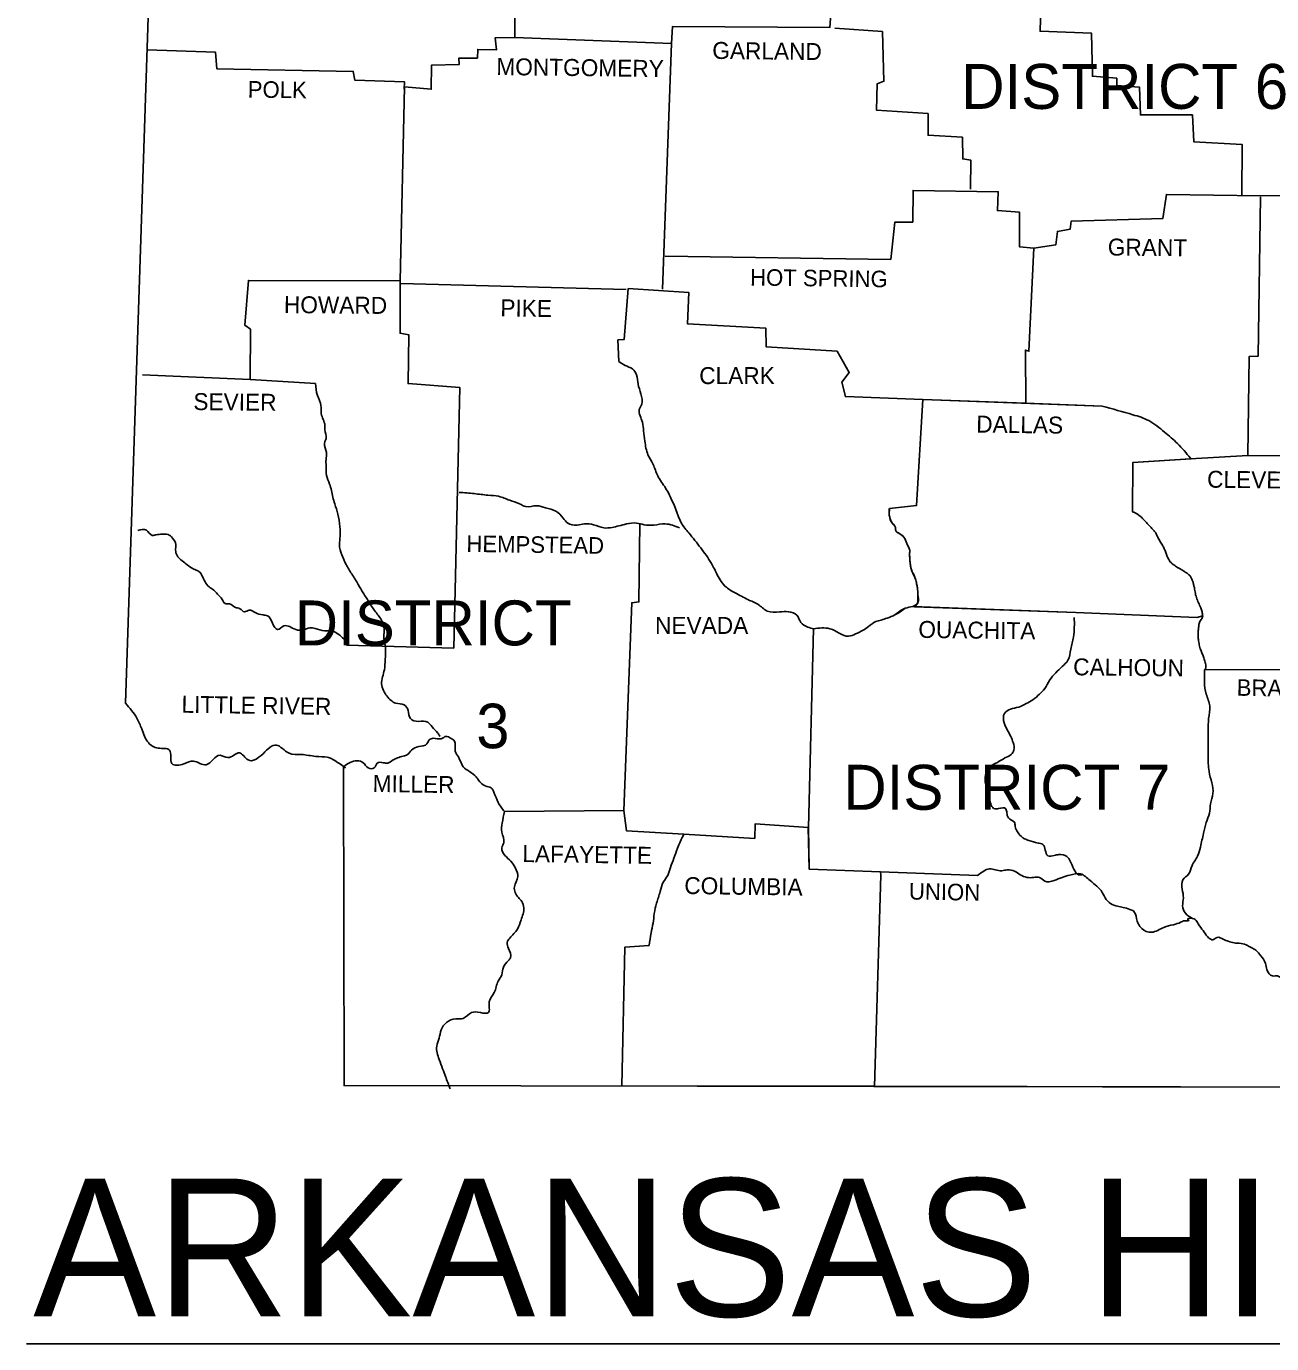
# Model space of a CAD drawing. Extents: x -17742 to 32032, y -17264 to 5867.
# Drawn here: x -17742 to -16002, y -10461 to -8621 of the extents above; entities that cross this region are included whole.
import ezdxf

# ---------------------------------------------------------------- set-up
doc = ezdxf.new("R2010")
doc.units = 0
for name, color, linetype in [('1', 7, 'Continuous'), ('2', 7, 'Continuous'), ('3', 7, 'Continuous'), ('R_Annotation', 7, 'Continuous')]:
    doc.layers.add(name, color=color, linetype=linetype)

msp = doc.modelspace()

# ---------------------------------------------------------------- linework, layer by layer
at = {"layer": '1'}
msp.add_line((-17741.9, -10460.7), (-14228.8, -10460.7), dxfattribs=at)
for points in [[(-17667.8, -7158.5), (-17553.9, -8073.2), (-17603.4, -9566.3)], [(-17058.6, -8314.8), (-17059.7, -8636.8), (-17087.2, -8637.3), (-17085, -8653.9), (-17111.4, -8653.3), (-17111.9, -8665.4), (-17137.8, -8665.4), (-17137.3, -8674.2), (-17175.8, -8675.3), (-17176.3, -8708.9), (-17213.8, -8705.6), (-17219.8, -8976.4), (-17431.7, -8975.8), (-17436.7, -9038.6), (-17428.9, -9044.1), (-17429.5, -9114.5), (-17579.7, -9107.9)], [(-16434.5, -8557), (-16614.4, -8551.5), (-16619.4, -8622.5), (-16839.5, -8621.4), (-16840.6, -8645.1)], [(-16385.5, -8555.3), (-16323.8, -8559.2), (-16326, -8628), (-16253.9, -8630.7), (-16252.8, -8690.7), (-16218.7, -8693.5), (-16218.7, -8703.9), (-16186.8, -8706.1), (-16185.7, -8744.7), (-16113.1, -8744.7), (-16110.9, -8782.6), (-16043.7, -8785.9), (-16044.3, -8857.5)], [(-16612.8, -8623.6), (-16546.2, -8628.5), (-16544, -8697.9), (-16553.3, -8701.2), (-16554.4, -8738.1), (-16482.3, -8743), (-16482.3, -8773.3), (-16434.5, -8776), (-16433.9, -8806.3), (-16422.4, -8808), (-16422.9, -8848.7)], [(-16840.6, -8645.1), (-17059.7, -8636.8)], [(-16840.6, -8645.1), (-16853.3, -8987.9)], [(-17573.1, -8653.9), (-17477.9, -8657.2), (-17475.7, -8680.3), (-17285.3, -8684.1), (-17283.1, -8696.2), (-17213.8, -8698.4), (-17214.3, -8708.9)], [(-15387.7, -8794.2), (-15595.7, -8788.7), (-15596.8, -8856.4), (-16017.8, -8858)], [(-16849.4, -8942.2), (-16534.6, -8946.6), (-16528.6, -8894.4), (-16503.8, -8894.4), (-16503.3, -8850.3), (-16384.4, -8852), (-16385.5, -8878.4), (-16354.7, -8880.6), (-16354.7, -8929), (-16334.8, -8930.7)], [(-16334.8, -8930.7), (-16304, -8926.3), (-16301.8, -8907.6), (-16283.7, -8904.3), (-16282.6, -8893.3), (-16154.3, -8889.4), (-16149.4, -8855.8), (-16017.8, -8858)], [(-16017.8, -8859.1), (-16021.1, -9081.5), (-16033.8, -9082), (-16035.5, -9220.2)], [(-16334.8, -8930.7), (-16341.4, -9074.9), (-16346.4, -9073.2), (-16345.9, -9148.1)], [(-17219.8, -8976.4), (-17219.8, -9049.6), (-17207.7, -9051.8), (-17208.8, -9120), (-17136.2, -9125.5), (-17145, -9489.3), (-17294.7, -9485.4)], [(-17218.7, -8980.2), (-16903.9, -8988.5)], [(-17429.5, -9114.5), (-17338.1, -9120)], [(-16489.7, -9142.2), (-16489.7, -9142.4)], [(-16885.2, -9315.4), (-16886.3, -9424.9), (-16896.2, -9426), (-16907.2, -9716)], [(-16096, -9519.6), (-15847.2, -9519)], [(-17299.1, -9655), (-17298, -10100.2), (-16558.1, -10101.4)], [(-16823.6, -9749.1), (-16903.4, -9744.7), (-16907.2, -9716), (-17074, -9717.7)], [(-16413.5, -9806.9), (-16548.7, -9801.8)], [(-16558.1, -10101.4), (-15280.9, -10103.5)]]:
    msp.add_lwpolyline(points, dxfattribs=at)
for points in [[(-17338.1, -9120), (-17335.4, -9136.5), (-17330.4, -9150.8), (-17329.9, -9161.8), (-17324.9, -9178.3), (-17324.9, -9184.4), (-17323.3, -9196.5), (-17325.5, -9203.1), (-17322.7, -9216.3), (-17323.3, -9226.2), (-17323.3, -9234.5), (-17322.7, -9248.2), (-17318.3, -9260.3), (-17313.9, -9278.5), (-17311.2, -9287.9), (-17306.8, -9302.2), (-17304, -9319.8), (-17303.5, -9333), (-17304.6, -9345.1), (-17301.3, -9358.9), (-17295.2, -9372.6), (-17287.5, -9385.8), (-17278.2, -9400.7), (-17271.5, -9412.2), (-17263.3, -9424.9), (-17256.7, -9435.4), (-17246.8, -9448.6), (-17242.4, -9459.6), (-17242.4, -9475), (-17240.2, -9489.3), (-17240.7, -9505.3), (-17241.8, -9519.6), (-17245.7, -9539.4), (-17242.9, -9548.7), (-17232.5, -9562.5), (-17225.9, -9566.3), (-17214.3, -9568.5), (-17208.8, -9576.3), (-17205.5, -9587.8), (-17193.9, -9591.7), (-17181.3, -9592.8), (-17175.2, -9599.4), (-17167, -9608.2), (-17164.2, -9612.6)], [(-17137.3, -9271.9), (-17116.3, -9273.6), (-17097.1, -9275.8), (-17082.2, -9277.4), (-17066.8, -9282.9), (-17053.1, -9287.9), (-17044.3, -9291.7), (-17029.4, -9290.6), (-17016.7, -9293.4), (-17002.4, -9298.3), (-16992, -9307.7), (-16985.4, -9314.8), (-16972.7, -9317.6), (-16962.2, -9315.9), (-16949.6, -9317), (-16935.3, -9321.4), (-16923.7, -9320.9), (-16914.4, -9318.7), (-16903.4, -9315.9), (-16889.6, -9314.8), (-16879.1, -9317), (-16865.4, -9317.6), (-16849.4, -9315.9), (-16829.6, -9321.4)], [(-17586.3, -9325.3), (-17574.2, -9324.7), (-17566, -9331.9), (-17561, -9331.3), (-17552.2, -9330.2), (-17544, -9330.8), (-17537.9, -9335.7), (-17533, -9344.6), (-17533.5, -9352.8), (-17533, -9356.1), (-17529.1, -9363.3), (-17522.5, -9368.8), (-17515.4, -9374.3), (-17508.7, -9378.7), (-17497.7, -9385.8), (-17496.6, -9388), (-17492.2, -9396.8), (-17486.7, -9404), (-17480.1, -9408.4), (-17473, -9416.1), (-17469.7, -9419.4), (-17464.2, -9427.1), (-17458.1, -9427.7), (-17449.9, -9432.6), (-17443.8, -9434.3), (-17437.2, -9438.7), (-17430.6, -9436.5), (-17422.3, -9439.8), (-17411.3, -9443.1), (-17405.3, -9444.2), (-17398.1, -9454.6), (-17391, -9463.4), (-17382.2, -9458.5), (-17365.7, -9463.4), (-17355.2, -9464), (-17345.8, -9461.2), (-17338.7, -9461.8), (-17325.5, -9465.1), (-17317.2, -9465.1), (-17308.4, -9468.4), (-17300.2, -9475), (-17294.7, -9482.1), (-17294.7, -9485.4)], [(-16514.3, -9433.7), (-16528.6, -9443.1), (-16539.6, -9447.5), (-16547.8, -9450.2), (-16555.5, -9452.4), (-16565.4, -9459), (-16573.1, -9464.5), (-16583.6, -9469.5), (-16593.5, -9472.8), (-16605.6, -9468.9), (-16612.2, -9465.1), (-16619.4, -9462.3), (-16642.5, -9462.3)], [(-16528.6, -9443.1), (-16514.3, -9433.7), (-16503.8, -9431.5)], [(-16278.2, -9446.4), (-16279.3, -9473.9), (-16283.1, -9490.9), (-16287, -9506.4), (-16295.2, -9515.2), (-16304, -9524), (-16312.3, -9533.9), (-16319.4, -9546), (-16326.6, -9553.7), (-16335.9, -9561.4), (-16345.3, -9566.9), (-16355.8, -9571.8), (-16367.3, -9574.6), (-16375.6, -9580.7), (-16376.1, -9593.9), (-16366.8, -9612.6), (-16363.5, -9621.4), (-16362.4, -9631.8), (-16366.2, -9637.9), (-16375, -9642.8), (-16385.5, -9648.9), (-16394.8, -9654.4), (-16401.4, -9663.8), (-16402.5, -9676.4), (-16398.1, -9691.3), (-16396.5, -9700.1), (-16389.3, -9713.8), (-16383.8, -9713.3), (-16373.9, -9713.8), (-16372.8, -9716.6), (-16372.3, -9719.3), (-16370.1, -9726.5), (-16361.8, -9732.6), (-16360.7, -9738.1), (-16355.8, -9748.5), (-16347.5, -9755.7), (-16341.4, -9757.9), (-16328.8, -9761.7), (-16322.2, -9763.4), (-16315, -9779.3), (-16306.2, -9778.8), (-16299.6, -9777.7), (-16288.6, -9780.4), (-16283.7, -9787), (-16278.7, -9798), (-16272.1, -9805.8), (-16267.7, -9805.8)], [(-16098.7, -9444.2), (-16099.3, -9446.9), (-16100.9, -9449.6), (-16102.6, -9452.3), (-16103.7, -9455.2), (-16104.1, -9457.9), (-16104.5, -9460.6), (-16105, -9466.2), (-16105.2, -9471.7), (-16104.8, -9477.2), (-16103.5, -9484.7), (-16101.5, -9492), (-16100.5, -9494.8), (-16099.3, -9497.6), (-16098.2, -9500.3), (-16097.1, -9503.1), (-16096.1, -9506.2), (-16095.2, -9509.4), (-16094.6, -9512.5), (-16094.4, -9514.1), (-16094.3, -9515.7), (-16094.8, -9517.7), (-16095.3, -9518.6), (-16096, -9519.6)], [(-16096, -9519.6), (-16093.8, -9553.7), (-16088.8, -9570.2), (-16090.5, -9587.8), (-16091, -9604.9), (-16091, -9620.3), (-16091, -9635.1), (-16091, -9650.6), (-16089.9, -9661.6), (-16086.1, -9677.5), (-16084.4, -9692.4), (-16087.7, -9706.7), (-16089.4, -9719.9), (-16093.8, -9733.1), (-16097.6, -9748), (-16102, -9767.2), (-16105.9, -9779.9), (-16113.6, -9793.1), (-16118.6, -9805.2), (-16126.3, -9812.9), (-16127.4, -9826.1), (-16125.7, -9838.2), (-16126.8, -9849.2), (-16123, -9859.7), (-16113.1, -9866.8)], [(-17603.4, -9566.3), (-17587.5, -9587.3), (-17580.8, -9602.1), (-17571.5, -9621.4), (-17557.7, -9629.1), (-17541.8, -9631.8), (-17538.5, -9650.6), (-17522, -9651.1), (-17508.7, -9647.2), (-17490.6, -9652.2), (-17471.3, -9639), (-17460.3, -9642.3), (-17444.4, -9635.7), (-17432.3, -9645.6), (-17411.3, -9636.8), (-17392.6, -9624.7), (-17375, -9636.2), (-17358, -9637.9), (-17337.6, -9640.6), (-17321.6, -9641.7), (-17307.3, -9648.9), (-17296.9, -9656.1), (-17299.1, -9655)], [(-17299.1, -9655), (-17279.8, -9646.7), (-17271.5, -9649.4), (-17264.4, -9656.6), (-17256.1, -9656.6), (-17251.7, -9650), (-17243.5, -9649.4), (-17236.9, -9650), (-17229.7, -9645.6), (-17223.7, -9642.8), (-17215.4, -9640.1), (-17209.4, -9637.9), (-17203.9, -9631.8), (-17193.9, -9626.9), (-17182.4, -9623), (-17179.1, -9617.5), (-17173.6, -9615.3), (-17162.6, -9615.9), (-17155.4, -9612.6), (-17149.4, -9615.3), (-17143.9, -9619.2), (-17142.8, -9633.5), (-17138.4, -9641.2), (-17131.8, -9655), (-17122.4, -9662.1), (-17113.6, -9669.3), (-17110.3, -9673.7), (-17100.9, -9681.9), (-17092.7, -9684.7), (-17088.8, -9690.7), (-17082.8, -9705), (-17074, -9717.7)], [(-17074, -9717.7), (-17077.3, -9733.7), (-17077.8, -9746.3), (-17075.1, -9761.2), (-17077.8, -9768.3), (-17073.4, -9778.8), (-17065.2, -9787), (-17059.1, -9795.8), (-17055.3, -9808.5), (-17060.2, -9822.8), (-17054.7, -9837.7), (-17049.8, -9843.2), (-17047, -9852), (-17050.9, -9869), (-17055.8, -9881.7), (-17066.8, -9894.4), (-17070.1, -9900.4), (-17068.5, -9908.7), (-17065.7, -9921.9), (-17068.5, -9925.7), (-17075.6, -9935.1), (-17077.8, -9945.5), (-17082.8, -9954.3), (-17088.3, -9970.3), (-17095.4, -9983.5), (-17096.5, -9998.4), (-17107.5, -9998.4), (-17120.2, -9998.4), (-17131.8, -10006.6), (-17142.2, -10007.2), (-17154.9, -10012.1), (-17162.6, -10022.6), (-17165.3, -10034.1), (-17168.6, -10045.2), (-17165.3, -10063.9), (-17160.4, -10077.1), (-17156.5, -10087.5), (-17149.9, -10104.6)], [(-16413.5, -9806.9), (-16404.7, -9800.8), (-16396.5, -9797.5), (-16388.2, -9799.1), (-16379.4, -9800.2), (-16371.7, -9799.1), (-16361.8, -9800.8), (-16353.6, -9805.8), (-16344.2, -9809.6), (-16334.8, -9809.6), (-16326.6, -9809.6), (-16319.4, -9814.6), (-16306.2, -9814), (-16295.2, -9809.6), (-16284.2, -9806.3), (-16269.4, -9804.6), (-16256.1, -9814), (-16246.8, -9821.7), (-16239.1, -9830.5), (-16233.6, -9840.4), (-16227.5, -9845.9), (-16217.6, -9849.8), (-16209.9, -9851.4), (-16200.6, -9854.2), (-16195.6, -9856.4), (-16191.2, -9866.8), (-16184, -9881.1), (-16170.3, -9886.1), (-16153.2, -9879.5), (-16139.5, -9875.6), (-16129.6, -9872.3), (-16123.5, -9870.1), (-16118, -9869.6), (-16119.7, -9868.5), (-16113.1, -9866.8), (-16107, -9871.2), (-16103.1, -9877.3), (-16096.5, -9886.1), (-16090.5, -9893.8), (-16084.4, -9896.6), (-16078.4, -9893.3), (-16070.1, -9896), (-16063, -9898.8), (-16054.7, -9901), (-16047.6, -9901.5), (-16038.2, -9903.7), (-16031, -9907.6), (-16024.4, -9911.4), (-16017.8, -9918.6), (-16011.2, -9929.6), (-16009, -9938.4), (-16001.3, -9947.2), (-15994.2, -9947.2), (-15983.7, -9961.5), (-15979.9, -9967), (-15971.6, -9976.9), (-15965.6, -9976.9), (-15954, -9979.1)]]:
    msp.add_spline(points, degree=3, dxfattribs=at)
at = {"layer": 'R_Annotation'}
for p, q in [((-16345.9, -9148.1), (-16345.9, -9147.4)), ((-16239.1, -9151.4), (-16345.8, -9147.5)), ((-16115.3, -9224.6), (-16115.8, -9224)), ((-16558.1, -10101.4), (-16557.1, -10101.4))]:
    msp.add_line(p, q, dxfattribs=at)
for points in [[(-16914.4, -9089.2), (-16915.5, -9058.9), (-16906.7, -9058.4), (-16901.2, -8987.4), (-16816.4, -8992.9), (-16818.6, -9036.4), (-16709.1, -9042.4), (-16708.5, -9068.8), (-16609.5, -9074.9), (-16592.4, -9104.6), (-16602.9, -9117.8), (-16597.9, -9138.2), (-16489.8, -9142.2)], [(-16239.1, -9151.4), (-16489.8, -9142.2), (-16489.7, -9142.4), (-16498.3, -9290.1), (-16536.3, -9294.5)], [(-16345.9, -9147.4), (-16489.8, -9142.2), (-16498.3, -9290.1), (-16536.3, -9294.5)], [(-16345.8, -9147.5), (-16345.9, -9148.1)], [(-16196.7, -9298.9), (-16196.2, -9230.1), (-16114.7, -9225.1)], [(-16196.7, -9298.9), (-16196.2, -9230.1), (-16115.8, -9225.2)], [(-16115.8, -9225.1), (-16035.5, -9220.2), (-15840.6, -9221.3), (-15839.5, -9221.3), (-15839, -9290.1), (-15850.5, -9290.6), (-15847.2, -9519), (-15852.7, -9672), (-15864.8, -9679.7)], [(-16115.8, -9225.2), (-16115.8, -9225.1), (-16115.3, -9224.6)], [(-16503.8, -9431.5), (-16276, -9439.8), (-16107, -9446.4), (-16098.7, -9444.2)], [(-16501.2, -9431.6), (-16276, -9439.8), (-16107, -9446.4), (-16098.7, -9444.2)], [(-16649.6, -9739.7), (-16642.5, -9462.3)], [(-16823.6, -9749.1), (-16724.5, -9755.1), (-16723.9, -9734.8), (-16649.6, -9739.7), (-16649.9, -9739.7), (-16648.5, -9798), (-16548.7, -9801.8), (-16548.5, -9806.4), (-16557.1, -10101.4)], [(-16557.1, -10101.4), (-16548.5, -9806.4), (-16548.7, -9801.8), (-16648.5, -9798), (-16649.6, -9739.7), (-16723.9, -9734.8), (-16724.5, -9755.1), (-16823.5, -9749.1)], [(-16558.1, -10101.3), (-16910, -10100.7), (-16906.1, -9907), (-16872, -9904.8)], [(-16872, -9904.8), (-16906.1, -9907), (-16910, -10100.7), (-16558.1, -10101.4)], [(-15915.6, -10102.4), (-16558.1, -10101.3)]]:
    msp.add_lwpolyline(points, dxfattribs=at)
for points in [[(-16642.5, -9462.3), (-16650.2, -9460.1), (-16660.1, -9453.5), (-16665.6, -9443.6), (-16677.2, -9438.7), (-16689.8, -9438.7), (-16706.9, -9437.6), (-16720.1, -9428.2), (-16731.6, -9422.7), (-16749.8, -9413.3), (-16764.1, -9404.5), (-16776.8, -9386.9), (-16785, -9371), (-16799.9, -9349.5), (-16816.4, -9328.6), (-16826.9, -9314.8), (-16835.1, -9294.5), (-16839.5, -9284.6), (-16848.9, -9265.9), (-16859.9, -9248.8), (-16866.5, -9232.8), (-16873.6, -9219.6), (-16878, -9200.4), (-16879.7, -9186.1), (-16881.3, -9173.9), (-16885.7, -9156.3), (-16882.4, -9148.6), (-16883.5, -9134.3), (-16887.4, -9120.6), (-16889.6, -9107.9), (-16895.1, -9099.6), (-16905.6, -9094.7), (-16914.4, -9089.2)], [(-16115.8, -9224), (-16134, -9203.7), (-16152.1, -9187.7), (-16174.1, -9171.7), (-16196.2, -9163.5), (-16239.1, -9151.4)], [(-16115.8, -9224), (-16134, -9203.7), (-16152.1, -9187.7), (-16174.1, -9171.7), (-16196.2, -9163.5), (-16239.1, -9151.4)], [(-16536.3, -9294.5), (-16536.9, -9299.7), (-16536.7, -9302.3), (-16536.3, -9304.9), (-16535.6, -9307.5), (-16534.7, -9310), (-16533.7, -9312.4), (-16532.4, -9314.8), (-16531.6, -9316), (-16530.5, -9317.1), (-16529.5, -9318.1), (-16528.6, -9319.2), (-16528, -9321), (-16527.9, -9322.9), (-16527.7, -9324.8), (-16527.4, -9325.7), (-16526.9, -9326.4), (-16525.8, -9327.3), (-16524.5, -9328.1), (-16523.2, -9328.8), (-16522, -9329.7), (-16521, -9330.4), (-16520, -9331.2), (-16518, -9332.7), (-16516.2, -9334.3), (-16515.5, -9335.3), (-16514.8, -9336.3), (-16513.7, -9338.6), (-16512.8, -9341), (-16511.9, -9343.3), (-16511, -9345.7), (-16509.5, -9348.6), (-16508.8, -9350.1), (-16508.5, -9350.9), (-16508.2, -9351.7), (-16507.9, -9353.6), (-16508, -9355.5), (-16508.2, -9357.5), (-16508.2, -9359.4), (-16507.9, -9363.3), (-16507.7, -9367.1), (-16507.2, -9371.8), (-16506.9, -9374.1), (-16506.6, -9376.5), (-16505.3, -9380.7), (-16503.4, -9384.8), (-16501.5, -9388.8), (-16500, -9393), (-16498.3, -9399.6), (-16497.2, -9405.1), (-16496.6, -9414.4), (-16496.5, -9417.2), (-16496.5, -9420), (-16496.5, -9422.7), (-16496.6, -9424.1), (-16496.6, -9425.5), (-16497.1, -9427), (-16498.2, -9428.7), (-16501.2, -9431.6)], [(-16536.3, -9294.5), (-16536.3, -9304.9), (-16532.4, -9314.8), (-16528.6, -9319.2), (-16526.9, -9326.4), (-16522, -9329.7), (-16514.8, -9336.3), (-16511, -9345.7), (-16508.2, -9351.7), (-16508.2, -9359.4), (-16507.7, -9367.1), (-16506.6, -9376.5), (-16500, -9393), (-16498.3, -9399.6), (-16497.2, -9405.1), (-16496.6, -9414.4), (-16496.6, -9425.5), (-16503.8, -9431.5)], [(-16098.7, -9444.2), (-16099.7, -9438.7), (-16101.5, -9433.2), (-16103, -9429.5), (-16104.6, -9426), (-16106.2, -9422.5), (-16107.5, -9418.9), (-16108.6, -9414.9), (-16109.3, -9410.9), (-16110, -9406.9), (-16110.9, -9402.9), (-16112, -9398.6), (-16113.3, -9394.3), (-16115.2, -9390.4), (-16118, -9386.9), (-16118.9, -9386.2), (-16119.7, -9385.5), (-16121.5, -9384.3), (-16125.2, -9382), (-16136.7, -9374.8), (-16141.2, -9371.6), (-16145, -9367.7), (-16145.8, -9366.5), (-16146.5, -9365.2), (-16147.8, -9362.6), (-16149.9, -9357.3), (-16151.9, -9351.9), (-16154.3, -9346.8), (-16157.6, -9341.3), (-16160.9, -9335.7), (-16162.1, -9333.4), (-16163.2, -9330.9), (-16164.4, -9328.6), (-16165.9, -9326.4), (-16166.8, -9325.3), (-16167.8, -9324.3), (-16169.7, -9322.2), (-16173.6, -9318.1), (-16184, -9307.1), (-16186.8, -9304.6), (-16189.9, -9302.5), (-16193.2, -9300.6), (-16196.7, -9298.9)], [(-16143, -9370), (-16145, -9367.7), (-16145.8, -9366.5), (-16146.5, -9365.2), (-16147.8, -9362.6), (-16149.9, -9357.3), (-16151.9, -9351.9), (-16154.3, -9346.8), (-16157.6, -9341.3), (-16160.9, -9335.7), (-16162.1, -9333.4), (-16163.2, -9330.9), (-16164.4, -9328.6), (-16165.9, -9326.4), (-16166.8, -9325.3), (-16167.8, -9324.3), (-16169.7, -9322.2), (-16173.6, -9318.1), (-16184, -9307.1), (-16186.8, -9304.6), (-16189.9, -9302.5), (-16193.2, -9300.6), (-16196.7, -9298.9)], [(-16098.7, -9444.2), (-16099.7, -9438.7), (-16101.5, -9433.2), (-16103, -9429.5), (-16104.6, -9426), (-16106.2, -9422.5), (-16107.5, -9418.9), (-16108.6, -9414.9), (-16109.3, -9410.9), (-16110, -9406.9), (-16110.9, -9402.9), (-16112, -9398.6), (-16113.3, -9394.3), (-16115.2, -9390.4), (-16118, -9386.9), (-16118.9, -9386.2), (-16119.7, -9385.5), (-16121.5, -9384.3), (-16125.2, -9382), (-16136.7, -9374.8), (-16141.2, -9371.6), (-16143, -9370)], [(-16872, -9904.8), (-16869.2, -9887.2), (-16866.5, -9873.4), (-16864.8, -9860.2), (-16861.5, -9845.4), (-16856.6, -9829.4), (-16852.2, -9816.2), (-16846.1, -9806.9), (-16842.3, -9795.8), (-16837.3, -9782.6), (-16832.4, -9768.9), (-16823.5, -9749.1)], [(-16823.5, -9749.1), (-16832.4, -9768.9), (-16837.3, -9782.6), (-16842.3, -9795.8), (-16846.1, -9806.9), (-16852.2, -9816.2), (-16856.6, -9829.4), (-16861.5, -9845.4), (-16864.8, -9860.2), (-16866.5, -9873.4), (-16869.2, -9887.2), (-16872, -9904.8)]]:
    msp.add_spline(points, degree=3, dxfattribs=at)

# ---------------------------------------------------------------- texts
at = {"layer": '2'}
for s, height, rotation, p in [('GARLAND', 23.67, 359.3658, (-16783.9, -8666.5)), ('MONTGOMERY', 23.67, 359.2944, (-17085.5, -8689.1)), ('POLK', 23.11, 359.2152, (-17432.8, -8720.5)), ('GRANT', 23.67, 359.4032, (-16231.4, -8941.1)), ('HOT SPRING', 23.11, 359.2216, (-16731.1, -8983)), ('HOWARD', 23.67, 359.5145, (-17382.2, -9021.5)), ('PIKE', 23.66, 359.0452, (-17080, -9025.9)), ('SEVIER', 23.67, 359.4271, (-17508.7, -9156.9)), ('DALLAS', 23.66, 359.2462, (-16415.2, -9188.3)), ('CLEVELAND', 23.67, 359.3377, (-16092.7, -9265.3)), ('HEMPSTEAD', 23.11, 359.1885, (-17127.4, -9355)), ('OUACHITA', 23.67, 359.2043, (-16496.1, -9475)), ('CALHOUN', 23.67, 359.3634, (-16279.8, -9527.3)), ('BRADLEY', 23.11, 359.1449, (-16051.4, -9555.9)), ('LITTLE RIVER', 23.666, 359.1697, (-17525.3, -9579.6)), ('MILLER', 23.66, 359.1319, (-17258.3, -9690.2)), ('LAFAYETTE', 23.66, 359.1839, (-17049.2, -9788.1)), ('COLUMBIA', 23.66, 359.2125, (-16823, -9832.7)), ('UNION', 23.11, 358.9584, (-16509.3, -9840.4))]:
    msp.add_text(s, height=height, rotation=rotation, dxfattribs=at).set_placement(p)
for s, height, p in [('CLARK', 23.67, (-16802, -9120.7)), ('NEVADA', 23.67, (-16863.7, -9469.5)), ('ARKANSAS HIGHWAY DISTRICT 7', 192.623, (-17732.4, -10422.7))]:
    msp.add_text(s, height=height, dxfattribs=at).set_placement(p)
at = {"layer": '3'}
for s, height, p in [('DISTRICT 6', 62.74, (-16436.1, -8736.4)), ('DISTRICT', 62.74, (-17367.1, -9485.6)), ('3', 62.2, (-17113.4, -9629.2)), ('DISTRICT 7', 62.74, (-16600.8, -9715.1))]:
    msp.add_text(s, height=height, dxfattribs=at).set_placement(p)

doc.saveas('drawing.dxf')
